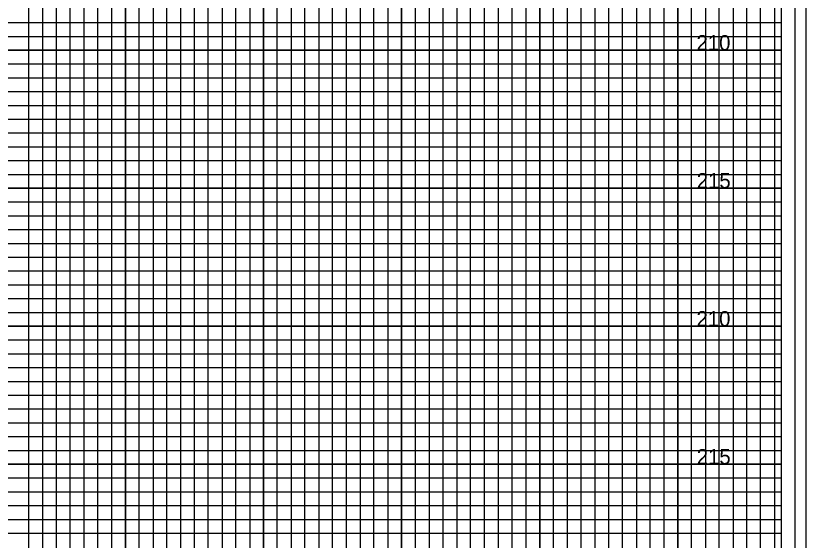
# Model space of a CAD drawing. Extents: x -4 to 103, y -2 to 492.
# Drawn here: x 74.78 to 103.4, y 173.9 to 192.9 of the extents above; entities that cross this region are included whole.
import ezdxf

# ---------------------------------------------------------------- set-up
doc = ezdxf.new("R2010")
doc.units = 0
for name, color, linetype in [('Old_Level_10', 7, 'Continuous'), ('Old_Level_5', 7, 'Continuous'), ('Old_Level_8', 7, 'Continuous'), ('Prop Dimension', 7, 'Continuous'), ('Prop XS Finish Grade Earthwork', 7, 'Continuous'), ('Prop XS SE Text', 7, 'Continuous'), ('Prop XSC Text', 7, 'Continuous')]:
    doc.layers.add(name, color=color, linetype=linetype)

msp = doc.modelspace()

# ---------------------------------------------------------------- linework, layer by layer
at = {"layer": 'Old_Level_10'}
for p, q in [((91.25, 141.65), (91.25, 205.075)), ((93.75, 141.65), (93.75, 205.075)), ((96.25, 141.65), (96.25, 205.075)), ((98.75, 141.65), (98.75, 205.075)), ((101.25, 141.65), (101.25, 205.075)), ((76.25, 141.65), (76.25, 203.65)), ((78.75, 141.65), (78.75, 203.65)), ((81.25, 141.65), (81.25, 203.65)), ((83.75, 141.65), (83.75, 203.65)), ((86.25, 141.65), (86.25, 203.65)), ((88.75, 141.65), (88.75, 203.65)), ((0, 191.65), (102.5, 191.65)), ((0, 189.15), (102.5, 189.15)), ((0, 186.65), (102.5, 186.65)), ((0, 184.15), (102.5, 184.15)), ((0, 181.65), (102.5, 181.65)), ((0, 179.15), (102.5, 179.15)), ((0, 176.65), (102.5, 176.65)), ((0, 174.15), (102.5, 174.15))]:
    msp.add_line(p, q, dxfattribs=at)
at = {"layer": 'Old_Level_5'}
msp.add_lwpolyline([(103.4, 209.05), (-3.5, 209.05), (-3.5, 139.225), (103.4, 139.225)], close=True, dxfattribs=at)
at = {"layer": 'Old_Level_8'}
for points in [[(91.25, 141.65), (91.25, 205.075), (93.75, 205.075), (93.75, 141.65)], [(96.25, 141.65), (96.25, 205.075), (98.75, 205.075), (98.75, 141.65)], [(101.25, 141.65), (101.25, 205.075)], [(76.25, 141.65), (76.25, 203.65), (78.75, 203.65), (78.75, 141.65)], [(81.25, 141.65), (81.25, 203.65), (83.75, 203.65), (83.75, 141.65)], [(86.25, 141.65), (86.25, 203.65), (88.75, 203.65), (88.75, 141.65)], [(0, 189.15), (102.5, 189.15), (102.5, 191.65), (0, 191.65)], [(0, 184.15), (102.5, 184.15), (102.5, 186.65), (0, 186.65)], [(0, 179.15), (102.5, 179.15), (102.5, 181.65), (0, 181.65)], [(0, 174.15), (102.5, 174.15), (102.5, 176.65), (0, 176.65)]]:
    msp.add_lwpolyline(points, dxfattribs=at)
at = {"layer": 'Prop Dimension'}
for points in [[(90.25, 141.65), (90.25, 205.075), (90.75, 205.075), (90.75, 141.65)], [(91.75, 141.65), (91.75, 205.075), (92.25, 205.075), (92.25, 141.65)], [(92.75, 141.65), (92.75, 205.075), (93.25, 205.075), (93.25, 141.65)], [(94.25, 141.65), (94.25, 205.075), (94.75, 205.075), (94.75, 141.65)], [(95.25, 141.65), (95.25, 205.075), (95.75, 205.075), (95.75, 141.65)], [(96.75, 141.65), (96.75, 205.075), (97.25, 205.075), (97.25, 141.65)], [(97.75, 141.65), (97.75, 205.075), (98.25, 205.075), (98.25, 141.65)], [(99.25, 141.65), (99.25, 205.075), (99.75, 205.075), (99.75, 141.65)], [(100.25, 141.65), (100.25, 205.075)], [(100.25, 205.075), (100.75, 205.075), (100.75, 141.65), (101.75, 141.65), (101.75, 205.075), (102.25, 205.075), (102.25, 141.65)], [(75.25, 141.65), (75.25, 203.65), (75.75, 203.65), (75.75, 141.65)], [(76.75, 141.65), (76.75, 203.65), (77.25, 203.65), (77.25, 141.65)], [(77.75, 141.65), (77.75, 203.65), (78.25, 203.65), (78.25, 141.65)], [(79.25, 141.65), (79.25, 203.65), (79.75, 203.65), (79.75, 141.65)], [(80.25, 141.65), (80.25, 203.65), (80.75, 203.65), (80.75, 141.65)], [(81.75, 141.65), (81.75, 203.65), (82.25, 203.65), (82.25, 141.65)], [(82.75, 141.65), (82.75, 203.65), (83.25, 203.65), (83.25, 141.65)], [(84.25, 141.65), (84.25, 203.65), (84.75, 203.65), (84.75, 141.65)], [(85.25, 141.65), (85.25, 203.65), (85.75, 203.65), (85.75, 141.65)], [(86.75, 141.65), (86.75, 203.65), (87.25, 203.65), (87.25, 141.65)], [(87.75, 141.65), (87.75, 203.65), (88.25, 203.65), (88.25, 141.65)], [(89.25, 141.65), (89.25, 203.65), (89.75, 203.65), (89.75, 141.65)], [(0, 192.15), (102.5, 192.15), (102.5, 192.65), (0, 192.65)], [(0, 190.65), (102.5, 190.65), (102.5, 191.15), (0, 191.15)], [(0, 189.65), (102.5, 189.65), (102.5, 190.15), (0, 190.15)], [(0, 188.15), (102.5, 188.15), (102.5, 188.65), (0, 188.65)], [(0, 187.15), (102.5, 187.15), (102.5, 187.65), (0, 187.65)], [(0, 185.65), (102.5, 185.65), (102.5, 186.15), (0, 186.15)], [(0, 184.65), (102.5, 184.65), (102.5, 185.15), (0, 185.15)], [(0, 183.15), (102.5, 183.15), (102.5, 183.65), (0, 183.65)], [(0, 182.15), (102.5, 182.15), (102.5, 182.65), (0, 182.65)], [(0, 180.65), (102.5, 180.65), (102.5, 181.15), (0, 181.15)], [(0, 179.65), (102.5, 179.65), (102.5, 180.15), (0, 180.15)], [(0, 178.15), (102.5, 178.15), (102.5, 178.65), (0, 178.65)], [(0, 177.15), (102.5, 177.15), (102.5, 177.65), (0, 177.65)], [(0, 175.65), (102.5, 175.65), (102.5, 176.15), (0, 176.15)], [(0, 174.65), (102.5, 174.65), (102.5, 175.15), (0, 175.15)]]:
    msp.add_lwpolyline(points, dxfattribs=at)
at = {"layer": 'Prop XS SE Text'}
msp.add_lwpolyline([(103, 207.65), (-2.8, 207.65), (-2.8, 140.65), (103, 140.65)], close=True, dxfattribs=at)
at = {"layer": 'Prop XSC Text'}
msp.add_lwpolyline([(102.5, 206.65), (0, 206.65), (0, 141.65), (102.5, 141.65)], close=True, dxfattribs=at)

# ---------------------------------------------------------------- texts
at = {"layer": 'Prop XS Finish Grade Earthwork'}
for s, p in [('210', (99.4296, 191.65)), ('215', (99.4383, 186.65)), ('210', (99.4296, 181.65)), ('215', (99.4383, 176.65))]:
    msp.add_text(s, height=0.55, dxfattribs=at).set_placement(p)

doc.saveas('drawing.dxf')
